(* Logix 5000 project; controller RIF_1769_DPS_L32E vendor 1 type 14 code 65 rev 13.34; software revision 13.03 *)

TASK MainTask (continuous, watchdog 500 ms) : MainProgram

MODULES
   Controller : vendor 1 type 14 code 65 (CompactLogixL35Controller 0, rev 13.34)
      LocalENB : 1769-L35E Ethernet Port (CompactLogixL35Ethernet 1, rev 13.1)
      Local : CompactBus (CompactVirtualAdapter 3, rev 13.1, Input RPI 2 ms)
         DPS : 1769-MODULE (Compact 1, rev 1.1, Output RPI 2 ms)
              Local:1:C.DATA[0]   // Low Byte = Slave Address (active if Address switches on hardware are "00" High Byte = 0 Force config from Master
              Local:1:C.DATA[2]   // Modules watchtog value to supervise the PLC (in Milliseconds)
              Local:1:C.DATA[3]   // Number of configuration bytes starting at Local:1:C.Data[8]
              Local:1:C.DATA[8]   // Module Definition: Module Type = 04 (Input Byte with consitency) Module Length = 03 (means 4 Byte lengh)
              Local:1:C.DATA[9]   // Module Definition Module Type = 05 (Input Word with consitency) Module Length = 01 (means 2 Word lengh)
              Local:1:C.DATA[10]   // Module Definition: Module Type = 06 (Output Byte with consitency) Module Length = 03 (means 4 Byte lengh)
              Local:1:C.DATA[11]   // Module Definition: Module Type = 07 (Output Word with consitency) Module Length = 01 (means 2 Word lengh)
END_MODULES

TYPE DPS_DEV_COMMAND_REGISTER :   // DPS Device Command Register
STRUCT
   Reserved0 : BOOL;   // Reserved
   Reserved1 : BOOL;   // Reserved
   Reserved2 : BOOL;   // Reserved
   Reserved3 : BOOL;   // Reserved
   Reserved4 : BOOL;   // Reserved
   NRdy : BOOL;   // Application Not Ready
   Init : BOOL;   // Init ( Warm boot )
   Reset : BOOL;   // Reset ( Cold boot )
   Reserved5 : SINT;   // Reserved
   Reserved6 : SINT;   // Reserved
   ExtStaSelect : SINT;   // Extra Status Select
END_STRUCT
END_TYPE

TYPE DPS_DEV_STATUS_REGISTER :   // Device Status Register
STRUCT
   Reserved0 : BOOL;
   Reserved1 : BOOL;
   Reserved2 : BOOL;
   Reserved3 : BOOL;
   Reserved4 : BOOL;
   Com : BOOL;   // Communication
   Run : BOOL;   // Running
   Rdy : BOOL;   // Ready
   Reserved5 : SINT;
   Reserved6 : SINT;
   Reserved7 : SINT;
END_STRUCT
END_TYPE

TYPE DPS_DPV1C1_RW_INDICATION :   // DPV1 C1 Read/Write Indication
STRUCT
   ReadReq : BOOL;   // Indicates a Read request
   WriteReq : BOOL;   // Indicates a Write request
   Reserved2 : BOOL;   // Reserved
   Reserved3 : BOOL;   // Reserved
   Reserved4 : BOOL;   // Reserved
   Reserved5 : BOOL;   // Reserved
   Reserved6 : BOOL;   // Reserved
   Reserved7 : BOOL;   // Reserved
   RwCnt : SINT;   // ReadWrite indication counter
   MaAdr : SINT;   // Address of reqesting master
   Slot : SINT;   // Requested Slot Number
   Index : SINT;   // Requested Index
   DataLen : SINT;   // Requested Data Length
   Reserved8 : SINT;   // Reserved
   Reserved9 : SINT;   // Reserved
END_STRUCT
END_TYPE

TYPE DPS_EXT_STAT_DPV1_C1_DIAG :   // Extended Status DPV1 Class 1 Diagnostics Information
STRUCT
   StaReqUsr : DINT;   // Status Request from User
   StaMsgSen : DINT;   // Status Messages Sent
   NegStaCnf : DINT;   // Negative Status Confirmations to User
   DiagReqUsr : DINT;   // Diagnosis Request from User
   DiagMsgSen : DINT;   // Diagnosis Messages Sent
   NegDiagCnf : DINT;   // Negative Diag Confirmations to User
   AlaReqUsr : DINT;   // Alarm Request from User
   AlaMsgSen : DINT;   // Alarm Messages Sent
   PosAlaCnf : DINT;   // Positive Alarm Confirmations to User
   NegAlaCnf : DINT;   // Negative Alarm Confirmations to User
   Requests : DINT;   // Requests
   ImmNegCnf : DINT;   // Immediate Negative Confirmations
   RW_Ind : DINT;   // R/W Indications to User
   PosRWResp : DINT;   // Positive R/W Responses from User
   NegRWResp : DINT;   // Negative R/W Responses from User
   AlaAckInd : DINT;   // Alarm Ack Indications
   AlaAckResp : DINT;   // Alarm Ack Responses
   AlaAckErr : DINT;   // Alarm Ack Errors
   ErrRespUsr : DINT;   // Erroneous Responses from User
   UnxRespUsr : DINT;   // Unexpected Responses from User
END_STRUCT
END_TYPE

TYPE DPS_EXT_STAT_FW_REV :   // Extended Status Firmware Revision
STRUCT
   FwName : SINT[8];
   FwType : SINT[8];
   FwVersion : SINT[8];
   FwDate : SINT[8];
END_STRUCT
END_TYPE

TYPE DPS_EXT_STAT_MAS_CFG :   // Extended Status Master Configuration Bytes
STRUCT
   CfgBytes : SINT[49];   // Configuration Bytes
END_STRUCT
END_TYPE

TYPE DPS_EXT_STAT_PARAM_DATA :   // Extened Status Slave Parameter Data
STRUCT
   PrmBytes : SINT[33];   // Parameter Data Bytes
END_STRUCT
END_TYPE

TYPE DPS_EXT_STAT_SLV_CFG :   // Slave Configuration Extended Status
STRUCT
   CfgBytes : SINT[49];   // Config Bytes
END_STRUCT
END_TYPE

TYPE DPS_FW_REVISION :   // Firmware Major/Minor Revision
STRUCT
   FwMinor : SINT;   // Firmware Minor Revison
   FwMajor : SINT;   // Firmware Major Revison
   Reserved1 : INT;
END_STRUCT
END_TYPE

TYPE DPS_INPUT_ARRAY :   // DPS Input Array
STRUCT
   DevStaReg : DPS_DEV_STATUS_REGISTER;   // Device Status Registers
   FwRev : DPS_FW_REVISION;   // Firmware Revision
   StaField : DPS_STATUS_FIELD;   // DPS Status Registers
   PBOutputData : SINT[380];   // PROFIBUS Output Data from Matser
END_STRUCT
END_TYPE

TYPE DPS_OUTPUT_ARRAY :   // DPS Output Array
STRUCT
   DevCmdReg : DPS_DEV_COMMAND_REGISTER;   // Device Command Register
   PBInputData : SINT[244];   // PROFIBIBUS Input Data for Master
END_STRUCT
END_TYPE

TYPE DPS_STATUS_FIELD :   // DPS Status Field
STRUCT
   ExtStaSelect : INT;   // Extended Status Select
   ExtStaLen : INT;   // Extended Status Length
   Baudrate : INT;   // Slave Baudrate
   Busaddress : SINT;   // Slave Bus Address
   UserFlags : SINT;   // User Flags
   Ident : INT;   // Slave Ident Number
   TaskState : INT;   // Slave Task State
   InputDataLen : INT;   // Slave Input Data Length
   OutputDataLen : INT;   // Slave Output Data Length
   ErrorCount : INT;   // Slave Error Count
   LastError : SINT;   // Slave Last Error
   Pad : SINT;   // Reserved
   WatchdogTime : INT;   // Slave Watchdog Time
   IrqCounter : INT;   // Slave Interrupt Counter
   C1Ind : DPS_DPV1C1_RW_INDICATION;   // DPV1 Class 1 Indication Registers
   ExtStatusInfo : SINT[96];   // Extened Status Information
END_STRUCT
END_TYPE

VAR_GLOBAL   (* controller tags *)
   DpsExtDpv1C1Diag : DPS_EXT_STAT_DPV1_C1_DIAG;
   DpsExtMasCfgBytes : DPS_EXT_STAT_MAS_CFG;
   DpsExtParamData : DPS_EXT_STAT_PARAM_DATA;
   DpsExtSlvCfgBytes : DPS_EXT_STAT_SLV_CFG;
   DpsExtStatFwRev : DPS_EXT_STAT_FW_REV;
   DpsInputArray : DPS_INPUT_ARRAY;
   DpsOutputArray : DPS_OUTPUT_ARRAY := (PBInputData[0] := 1, PBInputData[1] := 101);
END_VAR

PROGRAM MainProgram   (* routine attr 65 MainRoutine *)

ROUTINE DPS_Update_Ext_Data   (* ladder *)
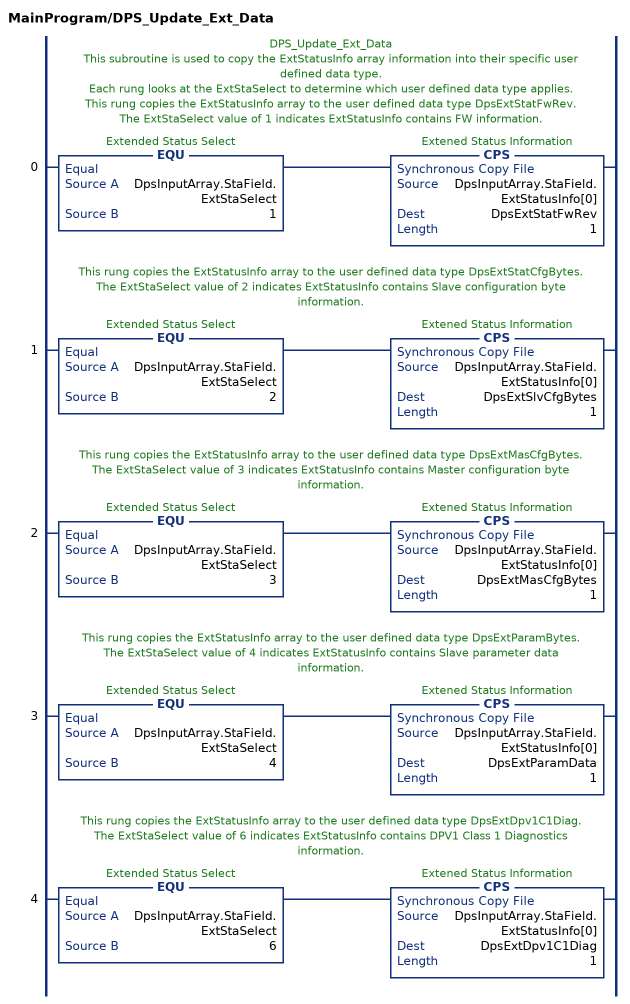
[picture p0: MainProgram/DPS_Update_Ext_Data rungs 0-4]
   // DPS_Update_Ext_Data
   // This subroutine is used to copy the ExtStatusInfo array information into their specific user defined data type.
   // Each rung looks at the ExtStaSelect to determine which user defined data type applies.
   // This rung copies the ExtStatusInfo array to the user defined data type DpsExtStatFwRev.
   // The ExtStaSelect value of 1 indicates ExtStatusInfo contains FW information.
   0: EQU(DpsInputArray.StaField.ExtStaSelect,1)CPS(DpsInputArray.StaField.ExtStatusInfo[0],DpsExtStatFwRev,1);
   // This rung copies the ExtStatusInfo array to the user defined data type DpsExtStatCfgBytes.
   // The ExtStaSelect value of 2 indicates ExtStatusInfo contains Slave configuration byte information.
   1: EQU(DpsInputArray.StaField.ExtStaSelect,2)CPS(DpsInputArray.StaField.ExtStatusInfo[0],DpsExtSlvCfgBytes,1);
   // This rung copies the ExtStatusInfo array to the user defined data type DpsExtMasCfgBytes.
   // The ExtStaSelect value of 3 indicates ExtStatusInfo contains Master configuration byte information.
   2: EQU(DpsInputArray.StaField.ExtStaSelect,3)CPS(DpsInputArray.StaField.ExtStatusInfo[0],DpsExtMasCfgBytes,1);
   // This rung copies the ExtStatusInfo array to the user defined data type DpsExtParamBytes.
   // The ExtStaSelect value of 4 indicates ExtStatusInfo contains Slave parameter data information.
   3: EQU(DpsInputArray.StaField.ExtStaSelect,4)CPS(DpsInputArray.StaField.ExtStatusInfo[0],DpsExtParamData,1);
   // This rung copies the ExtStatusInfo array to the user defined data type DpsExtDpv1C1Diag.
   // The ExtStaSelect value of 6 indicates ExtStatusInfo contains DPV1 Class 1 Diagnostics information.
   4: EQU(DpsInputArray.StaField.ExtStaSelect,6)CPS(DpsInputArray.StaField.ExtStatusInfo[0],DpsExtDpv1C1Diag,1);
END_ROUTINE

ROUTINE MainRoutine   (* ladder *)
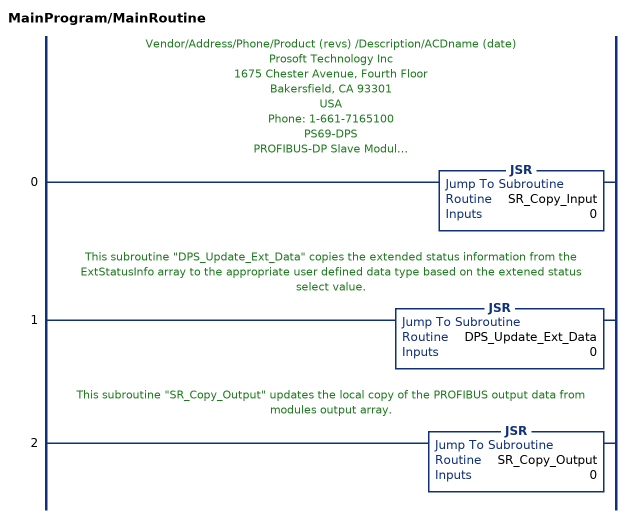
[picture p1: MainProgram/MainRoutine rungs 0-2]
   // Vendor/Address/Phone/Product (revs) /Description/ACDname (date)
   // Prosoft Technology Inc
   // 1675 Chester Avenue, Fourth Floor
   // Bakersfield, CA 93301
   // USA
   // Phone: 1-661-7165100
   // PS69-DPS
   // PROFIBUS-DP Slave Module
   // PS69_DPS_L32E.ACD (Rev1.0) (07/28/05)
   // Although this program has been developed with great care and intensively tested,
   // Prosoft Technology Inc cannot guarantee the suitability of this program
   // for any purpose not confirmed by us in writing.
   // We reserve the right to modify our products and their specifications at any time in as far as this contributes to technical progress.
   // The version of the manual supplied with the program applies.
   // This program is a basic example for the setup of the PROFIBUS-DP Slave communications module "PS69-DPS" in RSLogix5000.
   // This example will show simple PROFIBUS I/O data exchange.  For detailed information about setup and configuration
   // refer to the module user manual.
   // The subroutine "SR_Copy_Input" updates the local copy of the PROFIBUS input data from the modules input array.
   0: JSR(SR_Copy_Input,0);
   // This subroutine "DPS_Update_Ext_Data" copies the extended status information from the
   // ExtStatusInfo array to the appropriate user defined data type based on the extened status select value.
   1: JSR(DPS_Update_Ext_Data,0);
   // This subroutine "SR_Copy_Output" updates the local copy of the PROFIBUS output data from modules output array.
   2: JSR(SR_Copy_Output,0);
END_ROUTINE

ROUTINE SR_Copy_Input   (* ladder *)
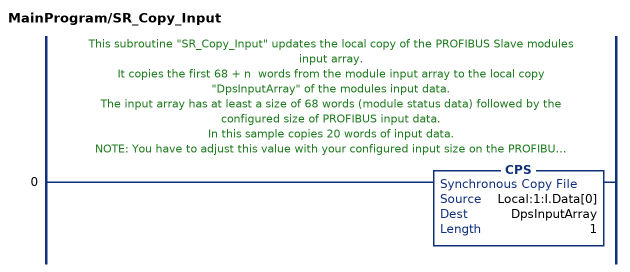
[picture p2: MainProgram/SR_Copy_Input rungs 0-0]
   // This subroutine "SR_Copy_Input" updates the local copy of the PROFIBUS Slave modules input array.
   // It copies the first 68 + n  words from the module input array to the local copy "DpsInputArray" of the modules input data.
   // The input array has at least a size of 68 words (module status data) followed by the configured size of PROFIBUS input data.
   // In this sample copies 20 words of input data.
   // NOTE: You have to adjust this value with your configured input size on the PROFIBUS network and the configured input size in the modules properties dialog Tab:General->Connection Parameter->Input.
   0: CPS(Local:1:I.Data[0],DpsInputArray,1);
END_ROUTINE

ROUTINE SR_Copy_Output   (* ladder *)
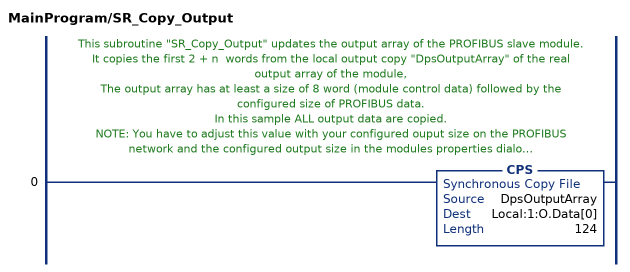
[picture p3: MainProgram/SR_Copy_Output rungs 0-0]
   // This subroutine "SR_Copy_Output" updates the output array of the PROFIBUS slave module.
   // It copies the first 2 + n  words from the local output copy "DpsOutputArray" of the real output array of the module,
   // The output array has at least a size of 8 word (module control data) followed by the configured size of PROFIBUS data.
   // In this sample ALL output data are copied.
   // NOTE: You have to adjust this value with your configured ouput size on the PROFIBUS network and the configured output size in the modules properties dialog Tab:General->Connection Paramter->Output.
   0: CPS(DpsOutputArray,Local:1:O.Data[0],124);
END_ROUTINE
END_PROGRAM
